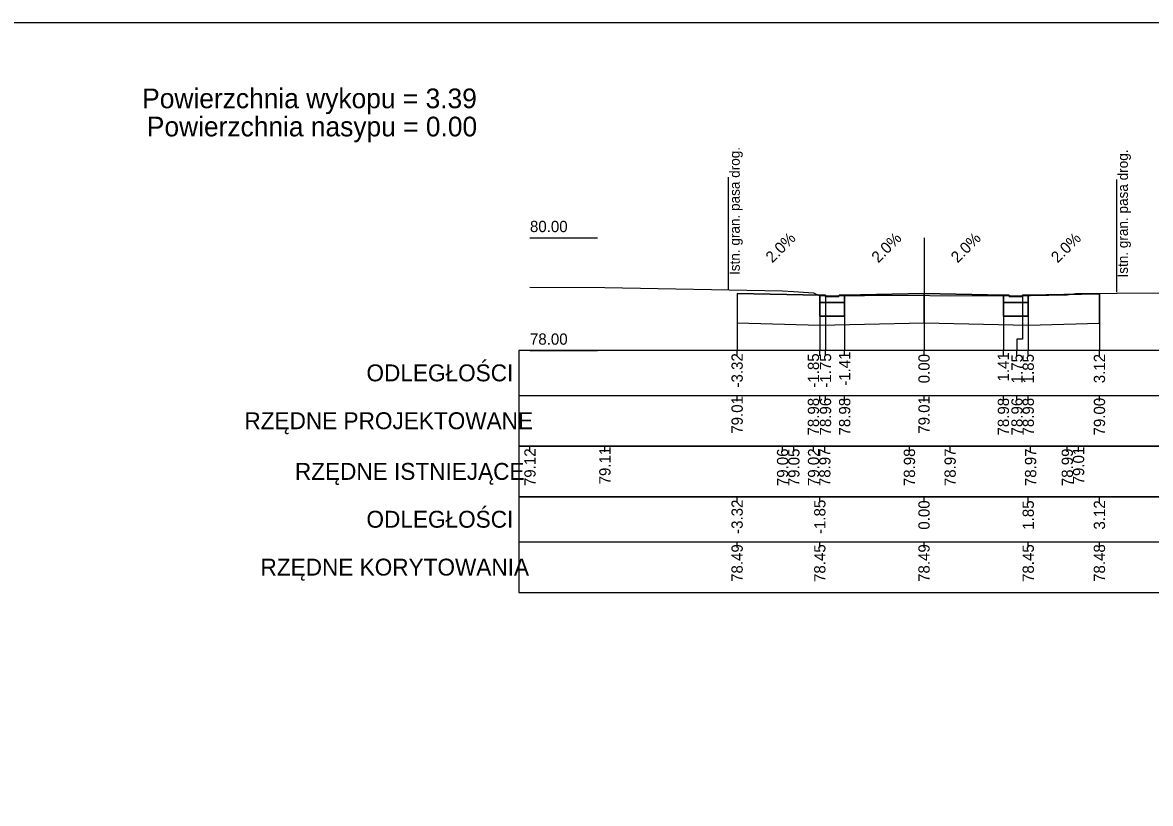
# Model space of a CAD drawing. Extents: x 7492871 to 7493499, y 5802964 to 5802992.
# Drawn here: x 7493391.54 to 7493411.57, y 5802978.41 to 5802992.28 of the extents above; entities that cross this region are included whole.
import ezdxf

# ---------------------------------------------------------------- set-up
doc = ezdxf.new("R2010")
doc.units = 0
for name, color, linetype in [('_wydruk', 7, 'Continuous'), ('d_pop_nasyp_opis', 7, 'Continuous'), ('d_pop_wykop_opis', 7, 'Continuous'), ('opisy_ramki_pop', 7, 'Continuous'), ('pop_comp_kostka', 7, 'Continuous'), ('pop_comp_lawa', 7, 'Continuous'), ('pop_comp_scieralna', 7, 'Continuous'), ('pop_granica_istn', 7, 'Continuous'), ('pop_opis', 7, 'Continuous'), ('pop_os', 7, 'Continuous'), ('pop_teren', 7, 'Continuous')]:
    doc.layers.add(name, color=color, linetype=linetype)

msp = doc.modelspace()

# ---------------------------------------------------------------- linework, layer by layer
msp.add_lwpolyline([(7493404.228, 5802987.467), (7493405.697, 5802987.437), (7493405.797, 5802987.437), (7493405.798, 5802987.417), (7493406.037, 5802987.417), (7493406.038, 5802987.437), (7493406.138, 5802987.437), (7493407.548, 5802987.466), (7493408.958, 5802987.437), (7493409.058, 5802987.437), (7493409.059, 5802987.417), (7493409.298, 5802987.417), (7493409.299, 5802987.437), (7493409.399, 5802987.437), (7493410.664, 5802987.463)])
at = {"layer": '_wydruk'}
msp.add_lwpolyline([(7492871.369, 5802992.281), (7493499.283, 5802992.281), (7493499.283, 5802963.881), (7492871.369, 5802963.881)], close=True, dxfattribs=at)
at = {"layer": 'opisy_ramki_pop'}
for points in [[(7493404.228, 5802986.947), (7493404.228, 5802986.659), (7493404.228, 5802986.659), (7493404.228, 5802986.459)], [(7493405.697, 5802986.908), (7493405.697, 5802986.659), (7493405.697, 5802986.659), (7493405.697, 5802986.459)], [(7493407.548, 5802986.946), (7493407.548, 5802986.659), (7493407.548, 5802986.659), (7493407.548, 5802986.459)], [(7493409.399, 5802986.908), (7493409.399, 5802986.659), (7493409.399, 5802986.659), (7493409.399, 5802986.459)], [(7493410.664, 5802986.942), (7493410.664, 5802986.659), (7493410.664, 5802986.659), (7493410.664, 5802986.459)]]:
    msp.add_lwpolyline(points, dxfattribs=at)
at = {"layer": 'pop_comp_kostka'}
for p, q in [((7493405.797, 5802987.437), (7493405.697, 5802987.437)), ((7493405.697, 5802987.437), (7493405.697, 5802987.307)), ((7493405.798, 5802987.417), (7493405.797, 5802987.437)), ((7493406.037, 5802987.417), (7493405.798, 5802987.417)), ((7493406.038, 5802987.437), (7493406.037, 5802987.417)), ((7493406.138, 5802987.437), (7493406.038, 5802987.437)), ((7493406.138, 5802987.307), (7493406.138, 5802987.437)), ((7493409.058, 5802987.437), (7493408.958, 5802987.437)), ((7493408.958, 5802987.437), (7493408.958, 5802987.307)), ((7493409.059, 5802987.417), (7493409.058, 5802987.437)), ((7493409.298, 5802987.417), (7493409.059, 5802987.417)), ((7493409.299, 5802987.437), (7493409.298, 5802987.417)), ((7493409.399, 5802987.437), (7493409.299, 5802987.437)), ((7493409.399, 5802987.307), (7493409.399, 5802987.437)), ((7493405.697, 5802987.307), (7493406.138, 5802987.307)), ((7493408.958, 5802987.307), (7493409.399, 5802987.307))]:
    msp.add_line(p, q, dxfattribs=at)
at = {"layer": 'pop_comp_lawa'}
for p, q in [((7493406.138, 5802987.307), (7493405.697, 5802987.307)), ((7493405.697, 5802987.307), (7493405.697, 5802987.067)), ((7493406.138, 5802987.067), (7493406.138, 5802987.307)), ((7493409.399, 5802987.307), (7493408.958, 5802987.307)), ((7493408.958, 5802987.307), (7493408.958, 5802987.067)), ((7493409.399, 5802987.067), (7493409.399, 5802987.307)), ((7493405.697, 5802987.067), (7493406.138, 5802987.067)), ((7493408.958, 5802987.067), (7493409.399, 5802987.067))]:
    msp.add_line(p, q, dxfattribs=at)
at = {"layer": 'pop_comp_scieralna'}
for p, q in [((7493405.697, 5802987.437), (7493404.228, 5802987.467)), ((7493404.228, 5802987.467), (7493404.228, 5802986.947)), ((7493405.697, 5802987.067), (7493405.697, 5802987.437)), ((7493407.548, 5802987.466), (7493406.138, 5802987.437)), ((7493406.138, 5802987.437), (7493406.138, 5802987.067)), ((7493407.548, 5802986.946), (7493407.548, 5802987.466)), ((7493408.958, 5802987.437), (7493407.548, 5802987.466)), ((7493407.548, 5802987.466), (7493407.548, 5802986.946)), ((7493408.958, 5802987.067), (7493408.958, 5802987.437)), ((7493410.664, 5802987.463), (7493409.399, 5802987.437)), ((7493409.399, 5802987.437), (7493409.399, 5802987.067)), ((7493410.664, 5802986.942), (7493410.664, 5802987.463)), ((7493406.138, 5802987.067), (7493405.697, 5802987.067)), ((7493409.399, 5802987.067), (7493408.958, 5802987.067)), ((7493404.228, 5802986.947), (7493405.697, 5802986.908)), ((7493405.697, 5802986.908), (7493407.548, 5802986.946)), ((7493407.548, 5802986.946), (7493409.399, 5802986.908)), ((7493409.399, 5802986.908), (7493410.664, 5802986.942))]:
    msp.add_line(p, q, dxfattribs=at)
at = {"layer": 'pop_granica_istn'}
for p, q in [((7493404.077, 5802988.036), (7493404.077, 5802989.536)), ((7493410.971, 5802987.991), (7493410.971, 5802989.491)), ((7493404.077, 5802987.536), (7493404.077, 5802988.036)), ((7493410.971, 5802987.491), (7493410.971, 5802987.991))]:
    msp.add_line(p, q, dxfattribs=at)
at = {"layer": 'pop_opis'}
for p, q in [((7493400.548, 5802988.459), (7493401.748, 5802988.459)), ((7493400.348, 5802986.459), (7493400.348, 5802984.759)), ((7493400.348, 5802986.459), (7493400.348, 5802984.759)), ((7493400.348, 5802986.459), (7493400.348, 5802984.759)), ((7493400.348, 5802986.459), (7493400.348, 5802984.759)), ((7493400.548, 5802986.459), (7493401.748, 5802986.459)), ((7493404.228, 5802986.359), (7493404.228, 5802986.459)), ((7493405.697, 5802986.359), (7493405.697, 5802986.459)), ((7493405.798, 5802986.359), (7493405.798, 5802986.459)), ((7493406.138, 5802986.359), (7493406.138, 5802986.459)), ((7493407.548, 5802986.359), (7493407.548, 5802986.459)), ((7493408.958, 5802986.359), (7493408.958, 5802986.459)), ((7493409.199, 5802986.359), (7493409.199, 5802986.459)), ((7493409.399, 5802986.359), (7493409.399, 5802986.459)), ((7493410.664, 5802986.359), (7493410.664, 5802986.459)), ((7493400.348, 5802985.659), (7493414.748, 5802985.659)), ((7493400.348, 5802985.659), (7493414.748, 5802985.659)), ((7493400.348, 5802985.659), (7493414.748, 5802985.659)), ((7493400.348, 5802985.659), (7493414.748, 5802985.659)), ((7493404.228, 5802985.559), (7493404.228, 5802985.659)), ((7493405.697, 5802985.559), (7493405.697, 5802985.659)), ((7493405.798, 5802985.559), (7493405.798, 5802985.659)), ((7493406.138, 5802985.559), (7493406.138, 5802985.659)), ((7493407.548, 5802985.559), (7493407.548, 5802985.659)), ((7493408.958, 5802985.559), (7493408.958, 5802985.659)), ((7493409.199, 5802985.559), (7493409.199, 5802985.659)), ((7493409.399, 5802985.559), (7493409.399, 5802985.659)), ((7493410.664, 5802985.559), (7493410.664, 5802985.659)), ((7493400.348, 5802984.759), (7493400.348, 5802983.859)), ((7493400.548, 5802984.659), (7493400.548, 5802984.759)), ((7493401.879, 5802984.659), (7493401.879, 5802984.759)), ((7493405.036, 5802984.659), (7493405.036, 5802984.759)), ((7493405.236, 5802984.659), (7493405.236, 5802984.759)), ((7493405.586, 5802984.659), (7493405.586, 5802984.759)), ((7493405.786, 5802984.659), (7493405.786, 5802984.759)), ((7493407.289, 5802984.659), (7493407.289, 5802984.759)), ((7493408.012, 5802984.659), (7493408.012, 5802984.759)), ((7493409.441, 5802984.659), (7493409.441, 5802984.759)), ((7493410.093, 5802984.659), (7493410.093, 5802984.759)), ((7493410.293, 5802984.659), (7493410.293, 5802984.759)), ((7493400.348, 5802983.859), (7493400.348, 5802982.159)), ((7493404.228, 5802983.759), (7493404.228, 5802983.859)), ((7493405.697, 5802983.759), (7493405.697, 5802983.859)), ((7493407.548, 5802983.759), (7493407.548, 5802983.859)), ((7493409.399, 5802983.759), (7493409.399, 5802983.859)), ((7493410.664, 5802983.759), (7493410.664, 5802983.859)), ((7493400.348, 5802983.059), (7493414.748, 5802983.059)), ((7493404.228, 5802982.959), (7493404.228, 5802983.059)), ((7493405.697, 5802982.959), (7493405.697, 5802983.059)), ((7493407.548, 5802982.959), (7493407.548, 5802983.059)), ((7493409.399, 5802982.959), (7493409.399, 5802983.059)), ((7493410.664, 5802982.959), (7493410.664, 5802983.059))]:
    msp.add_line(p, q, dxfattribs=at)
for points in [[(7493404.228, 5802987.467), (7493404.228, 5802986.659), (7493404.228, 5802986.659), (7493404.228, 5802986.459)], [(7493405.697, 5802987.437), (7493405.697, 5802986.659), (7493405.697, 5802986.659), (7493405.697, 5802986.459)], [(7493405.798, 5802987.417), (7493405.798, 5802986.659), (7493405.798, 5802986.659), (7493405.798, 5802986.459)], [(7493406.138, 5802987.437), (7493406.138, 5802986.659), (7493406.138, 5802986.659), (7493406.138, 5802986.459)], [(7493407.548, 5802987.466), (7493407.548, 5802986.659), (7493407.548, 5802986.659), (7493407.548, 5802986.459)], [(7493408.958, 5802987.437), (7493408.958, 5802986.659), (7493408.958, 5802986.659), (7493408.958, 5802986.459)], [(7493409.298, 5802987.417), (7493409.298, 5802986.659), (7493409.199, 5802986.659), (7493409.199, 5802986.459)], [(7493409.399, 5802987.437), (7493409.399, 5802986.659), (7493409.399, 5802986.659), (7493409.399, 5802986.459)], [(7493410.664, 5802987.463), (7493410.664, 5802986.659), (7493410.664, 5802986.659), (7493410.664, 5802986.459)]]:
    msp.add_lwpolyline(points, dxfattribs=at)
for points in [[(7493400.348, 5802986.459), (7493400.348, 5802984.759), (7493414.748, 5802984.759), (7493414.748, 5802986.459)], [(7493400.348, 5802986.459), (7493400.348, 5802984.759), (7493414.748, 5802984.759), (7493414.748, 5802986.459)], [(7493400.348, 5802986.459), (7493400.348, 5802984.759), (7493414.748, 5802984.759), (7493414.748, 5802986.459)], [(7493400.348, 5802986.459), (7493400.348, 5802984.759), (7493414.748, 5802984.759), (7493414.748, 5802986.459)], [(7493400.348, 5802984.759), (7493400.348, 5802983.859), (7493414.748, 5802983.859), (7493414.748, 5802984.759)], [(7493400.348, 5802983.859), (7493400.348, 5802982.159), (7493414.748, 5802982.159), (7493414.748, 5802983.859)]]:
    msp.add_lwpolyline(points, close=True, dxfattribs=at)
at = {"layer": 'pop_os'}
msp.add_line((7493407.548, 5802988.459), (7493407.548, 5802986.459), dxfattribs=at)
at = {"layer": 'pop_teren'}
msp.add_lwpolyline([(7493400.548, 5802987.581), (7493401.879, 5802987.574), (7493405.036, 5802987.516), (7493405.23, 5802987.507), (7493405.586, 5802987.479), (7493405.698, 5802987.426), (7493407.289, 5802987.437), (7493408.012, 5802987.43), (7493409.441, 5802987.433), (7493410.093, 5802987.446), (7493410.24, 5802987.467), (7493413.949, 5802987.499), (7493414.548, 5802987.498)], dxfattribs=at)

# ---------------------------------------------------------------- texts
at = {"layer": 'd_pop_nasyp_opis'}
msp.add_text('Powierzchnia nasypu = 0.00', height=0.35, dxfattribs=at).set_placement((7493393.743, 5802990.259))
at = {"layer": 'd_pop_wykop_opis'}
msp.add_text('Powierzchnia wykopu = 3.39', height=0.35, dxfattribs=at).set_placement((7493393.66, 5802990.759))
at = {"layer": 'pop_granica_istn'}
for p in [(7493404.275, 5802987.797), (7493411.169, 5802987.752)]:
    msp.add_text('Istn. gran. pasa drog.', height=0.18, rotation=90, dxfattribs=at).set_placement(p)
at = {"layer": 'pop_opis'}
for s, height, p in [('80.00', 0.2, (7493400.548, 5802988.559)), ('78.00', 0.2, (7493400.548, 5802986.559)), ('ODLEGŁOŚCI', 0.3, (7493397.644, 5802985.909)), ('ODLEGŁOŚCI', 0.3, (7493397.644, 5802985.909)), ('ODLEGŁOŚCI', 0.3, (7493397.644, 5802985.909)), ('ODLEGŁOŚCI', 0.3, (7493397.644, 5802985.909)), ('RZĘDNE PROJEKTOWANE', 0.3, (7493395.476, 5802985.059)), ('RZĘDNE PROJEKTOWANE', 0.3, (7493395.476, 5802985.059)), ('RZĘDNE PROJEKTOWANE', 0.3, (7493395.476, 5802985.059)), ('RZĘDNE PROJEKTOWANE', 0.3, (7493395.476, 5802985.059)), ('RZĘDNE ISTNIEJĄCE', 0.3, (7493396.373, 5802984.159)), ('ODLEGŁOŚCI', 0.3, (7493397.644, 5802983.309)), ('RZĘDNE KORYTOWANIA', 0.3, (7493395.762, 5802982.459))]:
    msp.add_text(s, height=height, dxfattribs=at).set_placement(p)
for s, rotation, p in [('2.0%', 45, (7493404.854, 5802988.002)), ('2.0%', 45, (7493406.735, 5802988.001)), ('2.0%', 45, (7493408.145, 5802988.001)), ('2.0%', 45, (7493409.923, 5802988)), ('-3.32', 90, (7493404.328, 5802985.799)), ('-1.85', 90, (7493405.684, 5802985.796)), ('-1.75', 90, (7493405.898, 5802985.796)), ('-1.41', 90, (7493406.238, 5802985.829)), ('0.00', 90, (7493407.648, 5802985.874)), ('1.41', 90, (7493409.058, 5802985.905)), ('1.75', 90, (7493409.299, 5802985.873)), ('1.85', 90, (7493409.499, 5802985.873)), ('3.12', 90, (7493410.764, 5802985.875)), ('79.01', 90, (7493404.328, 5802984.978)), ('78.98', 90, (7493405.684, 5802984.946)), ('78.96', 90, (7493405.898, 5802984.947)), ('78.98', 90, (7493406.238, 5802984.946)), ('79.01', 90, (7493407.648, 5802984.978)), ('78.98', 90, (7493409.058, 5802984.946)), ('78.96', 90, (7493409.299, 5802984.947)), ('78.98', 90, (7493409.499, 5802984.946)), ('79.00', 90, (7493410.764, 5802984.947)), ('79.12', 90, (7493400.648, 5802984.048)), ('79.11', 90, (7493401.979, 5802984.078)), ('79.06', 90, (7493405.136, 5802984.047)), ('79.05', 90, (7493405.336, 5802984.045)), ('79.02', 90, (7493405.686, 5802984.048)), ('78.97', 90, (7493405.886, 5802984.047)), ('78.98', 90, (7493407.389, 5802984.046)), ('78.97', 90, (7493408.112, 5802984.047)), ('78.97', 90, (7493409.541, 5802984.047)), ('78.99', 90, (7493410.193, 5802984.046)), ('79.01', 90, (7493410.393, 5802984.078)), ('-3.32', 90, (7493404.328, 5802983.199)), ('-1.85', 90, (7493405.797, 5802983.196)), ('0.00', 90, (7493407.648, 5802983.274)), ('1.85', 90, (7493409.499, 5802983.273)), ('3.12', 90, (7493410.764, 5802983.275)), ('78.49', 90, (7493404.328, 5802982.346)), ('78.45', 90, (7493405.797, 5802982.345)), ('78.49', 90, (7493407.648, 5802982.346)), ('78.45', 90, (7493409.499, 5802982.345)), ('78.48', 90, (7493410.764, 5802982.346))]:
    msp.add_text(s, height=0.2, rotation=rotation, dxfattribs=at).set_placement(p)

doc.saveas('drawing.dxf')
